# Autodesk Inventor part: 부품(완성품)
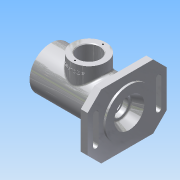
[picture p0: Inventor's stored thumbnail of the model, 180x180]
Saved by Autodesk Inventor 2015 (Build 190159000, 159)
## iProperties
Created: 2017-10
Part Number: 부품(완성품)
Material: 알루미늄 6061
Document SubType Name: Modeling
Designer: Administrator
Density: 2.7 g/cm^3
Appearance: 알루미늄 - 평지
Mass: 738.166 g
Surface Area: 653.383 cm^2
Volume: 273.395 cm^3
Author: Administrator
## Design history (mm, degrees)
sketch "스케치1"
  geometry: L1 (58, 27)-(58, -27); L2 (38, -47)-(-38, -47); L3 (38, 47)-(-38, 47); L4 (-58, -27)-(-58, 27); L5 (-38, 47)-(-58, 27); L6 (58, 27)-(38, 47); L7 (58, -27)-(38, -47); L8 (-38, -47)-(-58, -27); 7 further points
  constraints: 16 end point, 8 point on line, 2 midpoint, 1 horizontal, 1 horizontal alignment, 1 perpendicular, 1 vertical, 1 vertical alignment
  dimensions: "d6" = 20 distance of L3.end point (-58, 47); "d7" = 20 distance of L4.end point (-58, 47) (= d6); "d8" = 20 distance of L1.start point (58, 47) (= d6); "d9" = 20 distance of L3.start point (58, 47) (= d8); "d10" = 20 distance of L1.end point (58, -47) (= d6); "d11" = 20 distance of L2.start point (58, -47) (= d10); "d12" = 20 distance of L2.end point (-58, -47) (= d6); "d13" = 20 distance of L4.start point (-58, -47) (= d12); "d14" = 116 distance between parallel lines of L1 L4; "d15" = 94 distance between parallel lines of L2 L3
extrude "돌출1" new body sketch "스케치1" distance "d16" = 10; taper "d17" = 0 deg
sketch "스케치2"
  geometry: C1 r 35 at (0, 0); 1 further point
  constraints: 1 centre point, 1 coincident
  dimensions: "d18" = 70 diameter of C1
extrude "돌출2" join sketch "스케치2" distance "d19" = 3; taper "d20" = 0 deg
sketch "스케치3"
  geometry: L1 (13, -35)-(13, 35) reference; L2 (13, 0)-(-102, 0); L3 (0, 27)-(0, 47) reference; L4 (0, -27)-(0, 27) reference; L5 (-102, 31)-(-102, 0); L6 (-102, 31)-(13, 31); 1 further point
  constraints: 6 end point, 1 horizontal, 1 midpoint, 1 perpendicular, 1 point on line
  dimensions: "d21" = 115 distance of L2.start L2.end; "d22" = 62 diameter of L6 L2; "d23" = 115 distance of L5.start L6.end
revolve "회전1" sketch "스케치3" stored, may be unused: angle "d24" = 90 deg
sketch "스케치5"
  geometry: L1 (31, -102)-(-31, -102) reference; C1 r 25 at (0, -46); 1 further point
  constraints: 1 centre point, 1 vertical alignment
  dimensions: "d27" = 50 diameter of C1; "d28" = 56 distance from line of C1.centre L1
extrude "돌출3" join sketch "스케치5" distance "d29" = 47; taper "d30" = 0 deg
hole "구멍1" diameter "d33" = 40.376; stored, may be unused: countersink angle "d37" = 90 deg, drill point angle "d39" = 0 deg; dims "d31" = 10, "d32" = 10, "d34" = 9, "d35" = 4, "d36" = 2, "d38" = 9
sketch "스케치6"
  geometry: L1 (-93, 20.188)-(-93, -20.188) reference; L2 (13, -35)-(13, 35) reference; L3 (-93, 0)-(13, 0); L4 (-93, 0)-(-93, 24); L5 (-93, 24)-(-90, 24); L6 (-90, 24)-(-90, 20); L7 (-81, 20)-(-81, 17.5); L8 (-81, 17.5)-(-77.75, 17.5); L9 (-77.75, 17.5)-(-77.75, 18.5); L10 (-77.75, 18.5)-(-76, 18.5); L11 (-76, 18.5)-(-76, 17.5); L12 (-76, 17.5)-(-65, 17.5); L13 (-65, 17.5)-(-65, 23); L14 (-62, 26)-(-30, 26); L15 (-102, -20.188)-(-102, 20.188) reference; L16 (-27, 23)-(-27, 17.5); L17 (-27, 17.5)-(-16, 17.5); L18 (-16, 17.5)-(-16, 0); L19 (-90, 20)-(-81, 20); A1 r 3 centre (-62, 23) between (-62, 26) and (-65, 23); A2 r 3 centre (-30, 23) between (-27, 23) and (-30, 26); 3 further points
  constraints: 32 end point, 9 perpendicular, 8 point on line, 4 point on circle, 4 tangent, 2 centre point, 2 midpoint, 1 collinear, 1 equal radius, 1 horizontal, 1 vertical
  dimensions: "d40" = 3 distance of L4.end L5.end; "d41" = 21 distance from line of L7.start L15; "d42" = 26 distance from line of L11.end L15; "d44" = 1.75 distance of L9.end L10.end; "d45" = 60 horizontal distance of L17.end L10.end; "d46" = 38 distance of point (-65, 26) point (-27, 26); "d48" = 37 diameter of L10 L3; "d49" = 40 diameter of L19 L3; "d50" = 35 diameter of L8 L3; "d51" = 48 diameter of L5 L3; "d52" = 35 diameter of L17 L3; "d53" = 52 diameter of L14 L3; "d55" = 3 radius of A1
revolve "회전2" sketch "스케치6" stored, may be unused: angle "d54" = 90 deg
sketch "스케치7"
  geometry: L1 (-16, 17.5)-(-16, -17.5) reference; L2 (13, -35)-(13, 35) reference; L3 (13, 0)-(-16, 0); L4 (-16, 16.5)-(-14, 16.5); L5 (-11, 13.5)-(-11, 10); L6 (-11, 10)-(-8.3, 10); L7 (-8.3, 10)-(-8.3, 12.2); L8 (-8, 12.5)-(-1.7, 12.5); L9 (-1, 12.904)-(-1, 14.022); L10 (0.818, 16.779)-(13, 22); L11 (-16, 16.5)-(-16, 0); L12 (-1.7, 12.5)-(-1, 12.904); L13 (13, 22)-(13, 0); A1 r 3 centre (-14, 13.5) between (-11, 13.5) and (-14, 16.5); A2 r 0.3 centre (-8, 12.2) between (-8, 12.5) and (-8.3, 12.2); A3 r 3 centre (2, 14.022) between (0.818, 16.779) and (-1, 14.022); 5 further points
  constraints: 22 end point, 10 point on line, 6 point on circle, 6 tangent, 5 perpendicular, 3 centre point, 2 collinear, 2 midpoint, 1 horizontal
  dimensions: "d56" = 14 horizontal distance of point (-1, 16) L10.end; "d57" = 5 distance of L4.start point (-11, 16.5); "d58" = 32 diameter of point (-1, 16) L3; "d59" = 44 diameter of L10.end L3; "d60" = 7.3 distance of point (-8.3, 12.5) point (-1, 12.5); "d61" = 20 diameter of L6 L3; "d62" = 25 diameter of L8 L3; "d63" = 33 diameter of L4 L3; "d64" = 3 radius of A1; "d65" = 0.3 radius of A2; "d66" = 0.7 distance of L8.end point (-1, 12.5); "d67" = 30 deg angle of L8 L12; "d68" = 3 radius of A3
revolve "회전3" sketch "스케치7" stored, may be unused: angle "d69" = 90 deg
chamfer "모따기1" distance "d70" = 1; stored, may be unused: second distance "d71" = 2, angle "d72" = 45 deg
fillet "모깎기1" dims "d73" = 0.3
sketch "스케치8"
  geometry: L1 (-102, -31)-(-102, 31) reference; L2 (-21, 47)-(-71, 47) reference; 2 further points
  constraints: 1 other
  dimensions: "d74" = 56 distance from line of point (-46, 37) L1; "d75" = 10 distance from line of point (-46, 37) L2
feature "엠보싱1" sketch "스케치8" dims "d19" = 3, "d76" = 0.5, "d77" = 0
hole "구멍2" diameter "d80" = 32; stored, may be unused: countersink angle "d84" = 90 deg, drill point angle "d86" = 0 deg; dims "d78" = 10, "d79" = 10, "d81" = 9, "d82" = 4, "d83" = 2, "d85" = 47
sketch "스케치9" dims "d87" = 41
  geometry: 4 further points
  constraints: 2 horizontal alignment, 1 vertical alignment, 3 other
hole "구멍3" sketch "스케치9" at (-20.5, 0) diameter "d88" = 2.459; stored, may be unused: countersink angle "d92" = 90 deg, drill point angle "d94" = 118 deg; dims "d89" = 6, "d90" = 4, "d91" = 2, "d93" = 8
sketch "스케치10"
  geometry: L1 (50, -20)-(50, 20); L2 (42, 20)-(42, -20); L3 (-42, -20)-(-42, 20); L4 (-50, -20)-(-50, 20); L5 (38, -47)-(58, -27) reference; L6 (-38, -47)-(38, -47) reference; L7 (-58, -27)-(-38, -47) reference; L8 (-58, 27)-(-58, -27) reference; L9 (-38, 47)-(-58, 27) reference; L10 (38, 47)-(-38, 47) reference; L11 (58, 27)-(38, 47) reference; L12 (58, -27)-(58, 27) reference; C1 r 31 at (0, 0) reference; A1 r 4 centre (46, 20) between (50, 20) and (42, 20); A2 r 4 centre (46, -20) between (42, -20) and (50, -20); A3 r 4 centre (-46, 20) between (-42, 20) and (-50, 20); A4 r 4 centre (-46, -20) between (-50, -20) and (-42, -20); 3 further points
  constraints: 8 end point, 8 point on circle, 6 tangent, 4 centre point, 4 vertical, 2 equal radius, 2 horizontal alignment, 2 midpoint, 2 parallel
  dimensions: "d99" = 46 horizontal distance of point (0, 0) A1.centre; "d100" = 4 radius of A4; "d101" = 92 distance of A3.centre A1.centre; "d102" = 40 distance of A3.centre A4.centre
extrude "돌출4" cut sketch "스케치10" distance "d104" = 47; taper "d105" = 0 deg
chamfer "모따기2" distance "d106" = 1; stored, may be unused: second distance "d107" = 2, angle "d108" = 45 deg
fillet "모깎기2" dims "d109" = 3
node "솔리드1"
pattern_circular "원형 패턴1" dims angle "d96" = 360 deg
node "투영된 루프1"
